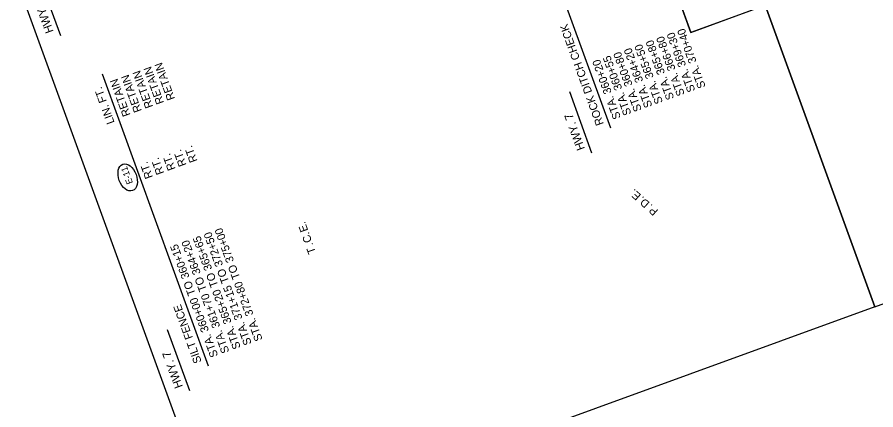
# Model space of a CAD drawing. Extents: x 960650 to 962115, y 1906452 to 1908757.
# Drawn here: x 960982 to 961626, y 1907002 to 1907297 of the extents above; entities that cross this region are included whole.
import ezdxf

# ---------------------------------------------------------------- set-up
doc = ezdxf.new("R2010")
doc.units = 0
for name, color, linetype in [('1', 7, 'Continuous'), ('44', 7, 'Continuous'), ('NO PLOT', 7, 'Continuous'), ('R_Draft', 7, 'Continuous')]:
    doc.layers.add(name, color=color, linetype=linetype)

msp = doc.modelspace()

# ---------------------------------------------------------------- linework, layer by layer
at = {"layer": '1'}
for p, q in [((961486.84, 1907285.2), (961369.64, 1907607.19)), ((961568.72, 1907315), (961486.84, 1907285.2)), ((961624.82, 1907079.46), (961542.56, 1907305.48))]:
    msp.add_line(p, q, dxfattribs=at)
msp.add_ellipse((961064.52, 1907176.45), major_axis=(-3.6, 9.89), ratio=0.638788, dxfattribs=at)
at = {"layer": '44'}
for p, q in [((961426.76, 1907213.38), (961344.33, 1907439.85)), ((961014.3, 1907282.61), (960997.6, 1907328.5)), ((961125.25, 1907035.06), (961045.63, 1907253.82)), ((961412.69, 1907194.76), (961395.98, 1907240.66)), ((961111.18, 1907016.44), (961094.48, 1907062.34))]:
    msp.add_line(p, q, dxfattribs=at)
at = {"layer": 'NO PLOT'}
for points in [[(962114.55, 1907257.7), (961568.91, 1908756.85), (961079.18, 1908578.6), (961182.12, 1908295.76), (961245.55, 1908318.85), (961390.91, 1907919.48), (961327.48, 1907896.39), (961425.36, 1907627.47), (961483.4, 1907648.6), (961600.59, 1907326.6), (961542.56, 1907305.48), (961624.82, 1907079.46)], [(962114.55, 1907257.7), (961568.91, 1908756.85), (961079.18, 1908578.6), (961182.12, 1908295.76), (961245.55, 1908318.85), (961390.91, 1907919.48), (961327.48, 1907896.39), (961425.36, 1907627.47), (961483.4, 1907648.6), (961600.59, 1907326.6), (961542.56, 1907305.48), (961624.82, 1907079.46)], [(962114.55, 1907257.7), (961568.91, 1908756.85), (961079.18, 1908578.6), (961182.12, 1908295.76), (961245.55, 1908318.85), (961390.91, 1907919.48), (961327.48, 1907896.39), (961425.36, 1907627.47), (961483.4, 1907648.6), (961600.59, 1907326.6), (961542.56, 1907305.48), (961624.82, 1907079.46)], [(962114.55, 1907257.7), (961568.91, 1908756.85), (961079.18, 1908578.6), (961182.12, 1908295.76), (961245.55, 1908318.85), (961390.91, 1907919.48), (961327.48, 1907896.39), (961425.36, 1907627.47), (961483.4, 1907648.6), (961600.59, 1907326.6), (961542.56, 1907305.48), (961624.82, 1907079.46)], [(962114.55, 1907257.7), (961568.91, 1908756.85), (961079.18, 1908578.6), (961182.12, 1908295.76), (961245.55, 1908318.85), (961390.91, 1907919.48), (961327.48, 1907896.39), (961425.36, 1907627.47), (961483.4, 1907648.6), (961600.59, 1907326.6), (961542.56, 1907305.48), (961624.82, 1907079.46)], [(961135.09, 1906901.21), (960730.12, 1908013.86), (960776.54, 1908030.76), (960709.57, 1908214.75), (960723.29, 1908219.74), (960649.59, 1908422.25), (961079.18, 1908578.6), (961182.12, 1908295.76), (961109.77, 1908269.43), (961255.13, 1907870.06), (961327.48, 1907896.39), (961425.36, 1907627.47), (961369.64, 1907607.19), (961486.84, 1907285.2), (961542.56, 1907305.48), (961624.82, 1907079.46)], [(961135.09, 1906901.21), (960730.12, 1908013.86), (960776.54, 1908030.76), (960709.57, 1908214.75), (960723.29, 1908219.74), (960649.59, 1908422.25), (961079.18, 1908578.6), (961182.12, 1908295.76), (961109.77, 1908269.43), (961255.13, 1907870.06), (961327.48, 1907896.39), (961425.36, 1907627.47), (961369.64, 1907607.19), (961486.84, 1907285.2), (961542.56, 1907305.48), (961624.82, 1907079.46)], [(961135.09, 1906901.21), (960730.12, 1908013.86), (960776.54, 1908030.76), (960709.57, 1908214.75), (960723.29, 1908219.74), (960649.59, 1908422.25), (961079.18, 1908578.6), (961182.12, 1908295.76), (961109.77, 1908269.43), (961255.13, 1907870.06), (961327.48, 1907896.39), (961425.36, 1907627.47), (961369.64, 1907607.19), (961486.84, 1907285.2), (961542.56, 1907305.48), (961624.82, 1907079.46)], [(961135.09, 1906901.21), (960730.12, 1908013.86), (960776.54, 1908030.76), (960709.57, 1908214.75), (960723.29, 1908219.74), (960649.59, 1908422.25), (961079.18, 1908578.6), (961182.12, 1908295.76), (961109.77, 1908269.43), (961255.13, 1907870.06), (961327.48, 1907896.39), (961425.36, 1907627.47), (961369.64, 1907607.19), (961486.84, 1907285.2), (961542.56, 1907305.48), (961624.82, 1907079.46)], [(961135.09, 1906901.21), (960730.12, 1908013.86), (960776.54, 1908030.76), (960709.57, 1908214.75), (960723.29, 1908219.74), (960649.59, 1908422.25), (961079.18, 1908578.6), (961182.12, 1908295.76), (961109.77, 1908269.43), (961255.13, 1907870.06), (961327.48, 1907896.39), (961425.36, 1907627.47), (961369.64, 1907607.19), (961486.84, 1907285.2), (961542.56, 1907305.48), (961624.82, 1907079.46)]]:
    msp.add_lwpolyline(points, close=True, dxfattribs=at)

# ---------------------------------------------------------------- texts
at = {"layer": '1'}
msp.add_text('E-11', height=4.8, rotation=109.99998, dxfattribs=at).set_placement((961068.52, 1907172.37))
at = {"layer": '44'}
for s, height, rotation, p in [('HWY. 7', 6.25, 110, (961009.09, 1907285.86)), ('ROCK DITCH CHECK', 6, 110, (961421.59, 1907216.6)), ('STA. 369+30', 6, 110, (961490.24, 1907241.59)), ('STA. 370+40', 6, 110, (961498.07, 1907244.43)), ('STA. 365+80', 6, 110, (961474.44, 1907235.83)), ('STA. 366+80', 6, 110, (961482.34, 1907238.71)), ('STA. 364+20', 6, 110, (961458.08, 1907229.88)), ('STA. 365+50', 6, 110, (961465.98, 1907232.75)), ('STA. 360+55', 6, 110, (961442.34, 1907224.15)), ('STA. 360+80', 6, 110, (961450.17, 1907227)), ('RETAIN', 6, 109.99998, (961091.91, 1907232.52)), ('RETAIN', 6, 109.99998, (961100.11, 1907235.5)), ('STA. 360+20', 6, 110, (961434.44, 1907221.28)), ('RETAIN', 6, 109.99998, (961075.16, 1907226.42)), ('RETAIN', 6, 109.99998, (961083.71, 1907229.54)), ('RETAIN', 6, 109.99998, (961066.75, 1907223.36)), ('LIN. FT.', 6, 109.99998, (961054.81, 1907217.63)), ('HWY. 7', 6.25, 110, (961407.48, 1907198.02)), ('RT.', 6, 109.99998, (961108.72, 1907185.86)), ('RT.', 6, 109.99998, (961116.92, 1907188.85)), ('RT.', 6, 109.99998, (961083.55, 1907176.7)), ('RT.', 6, 109.99998, (961091.96, 1907179.76)), ('RT.', 6, 109.99998, (961100.52, 1907182.88)), ('STA. 372+80 TO 375+00', 6, 109.99998, (961165.82, 1907054.92)), ('STA. 365+20 TO 365+65', 6, 109.99998, (961149.42, 1907048.96)), ('STA. 371+15 TO 372+50', 6, 109.99998, (961157.62, 1907051.94)), ('STA. 360+00 TO 360+15', 6, 109.99998, (961132.45, 1907042.78)), ('STA. 361+70 TO 364+20', 6, 109.99998, (961140.86, 1907045.84)), ('SILT FENCE      ', 6, 109.99998, (961120.09, 1907038.28)), ('HWY. 7', 6.25, 110, (961105.97, 1907019.7))]:
    msp.add_text(s, height=height, rotation=rotation, dxfattribs=at).set_placement(p)
at = {"layer": 'R_Draft'}
for s, rotation, p in [('E', 138.10209, (961449.96, 1907163.2)), ('.', 138.10209, (961445.95, 1907166.79)), ('.', 138.10209, (961452.14, 1907161.24)), ('D', 138.10209, (961456.36, 1907157.45)), ('.', 138.10209, (961458.54, 1907155.5)), ('P', 138.10209, (961462.76, 1907151.71)), ('.', 109.46478, (961198.2, 1907141.78)), ('E', 109.46478, (961199.99, 1907136.7)), ('C', 109.46478, (961202.86, 1907128.6)), ('.', 109.46478, (961200.97, 1907133.94)), ('.', 109.46478, (961203.83, 1907125.83)), ('T', 109.46478, (961205.79, 1907120.31))]:
    msp.add_text(s, height=6, rotation=rotation, dxfattribs=at).set_placement(p)

doc.saveas('drawing.dxf')
